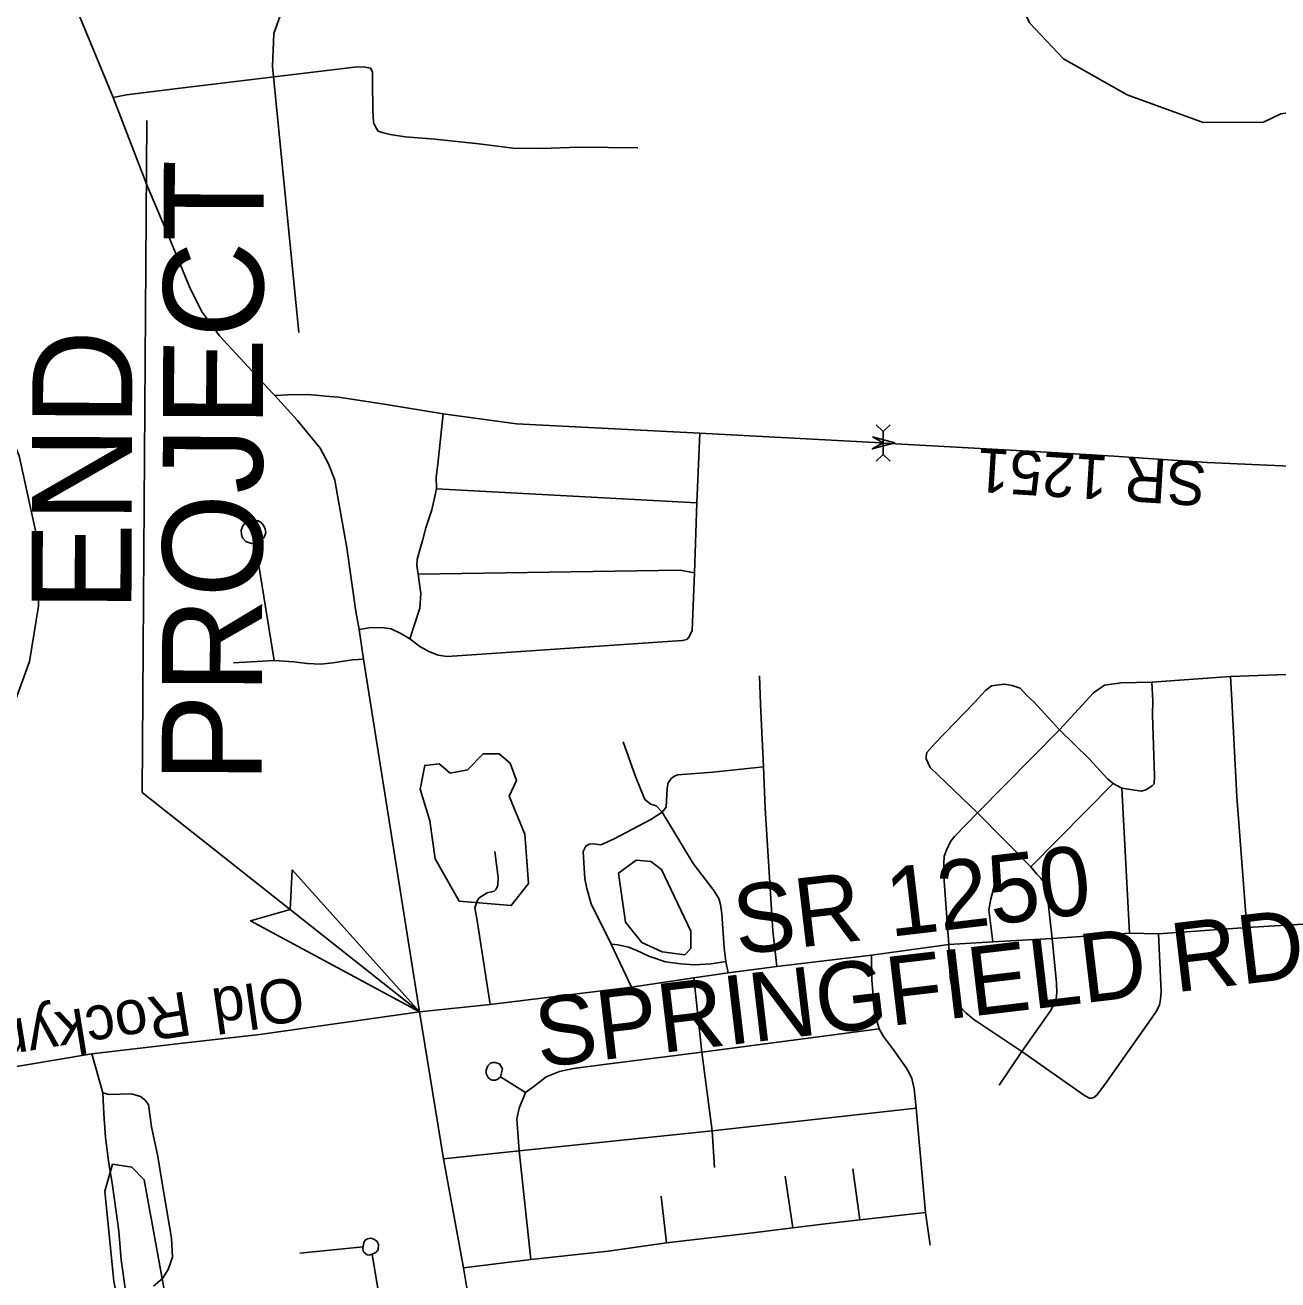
# Model space of a CAD drawing. Extents: x 2364794 to 2387902, y 795230 to 810426.
# Drawn here: x 2365657 to 2366377, y 801040 to 801761 of the extents above; entities that cross this region are included whole.
import ezdxf

# ---------------------------------------------------------------- set-up
doc = ezdxf.new("R2010")
doc.units = 0
for name, color, linetype in [('Default', 7, 'Continuous'), ('Old_Level_10', 7, 'Continuous'), ('Plot Label CELL', 7, 'Continuous'), ('User Information Notes CELL', 7, 'Continuous')]:
    doc.layers.add(name, color=color, linetype=linetype)

msp = doc.modelspace()

# ---------------------------------------------------------------- linework, layer by layer
at = {"layer": 'Default'}
for p, q in [((2365724.03, 801320.15), (2365726.66, 801706.52)), ((2366145.85, 801531.64), (2366149.86, 801527.81)), ((2366149.82, 801514.59), (2366149.86, 801527.81)), ((2366153.91, 801531.61), (2366149.86, 801527.81)), ((2366145.77, 801510.78), (2366149.82, 801514.59)), ((2366153.83, 801510.75), (2366149.82, 801514.59)), ((2365724.03, 801320.15), (2365883.31, 801194.17))]:
    msp.add_line(p, q, dxfattribs=at)
msp.add_lwpolyline([(2366143.64, 801524.67), (2366156.51, 801521.18), (2366143.62, 801517.77), (2366149.84, 801521.2)], close=True, dxfattribs=at)
msp.add_lwpolyline([(2365856.06, 801054.68), (2365854.33, 801054.22), (2365853.23, 801054.44), (2365852.59, 801054.87), (2365851.24, 801056.16), (2365850.8, 801057.91), (2365851, 801059.01)], dxfattribs=at)
at = {"layer": 'Old_Level_10'}
msp.add_lwpolyline([(2365810.14, 801275.75), (2365883.31, 801194.17), (2365786.22, 801246.47), (2365808.96, 801252.97)], close=True, dxfattribs=at)
at = {"layer": 'Plot Label CELL'}
for p, q in [((2366042.7, 801486.71), (2366044.51, 801526.78)), ((2366042.7, 801486.71), (2365893.12, 801494.87)), ((2366041.33, 801446.54), (2366042.7, 801486.71)), ((2365799.76, 801396.09), (2365788.94, 801463.66)), ((2365799.76, 801396.09), (2365776.41, 801394.77)), ((2366304.23, 801383.57), (2366349.47, 801386.86)), ((2366392.08, 801388.36), (2366349.47, 801386.86)), ((2366251.17, 801356.23), (2366204.14, 801308.59)), ((2366234.8, 801277.39), (2366282.05, 801325.43)), ((2366287.09, 801322.65), (2366282.05, 801325.43)), ((2366291.51, 801239.37), (2366287.09, 801322.65)), ((2366204.14, 801308.59), (2366234.8, 801277.39)), ((2366005.19, 801208.19), (2365993.61, 801232.94)), ((2366060.86, 801216.45), (2366059.49, 801222.98)), ((2366045.69, 801170.88), (2366040.96, 801213.55)), ((2366045.69, 801170.88), (2366147.48, 801184.4)), ((2365701.33, 801147.43), (2365695.01, 801169.89)), ((2366045.69, 801170.88), (2366051.52, 801125.68)), ((2366216.63, 801151.97), (2366229.58, 801171.31)), ((2365944.26, 801147.67), (2365929.96, 801156.75)), ((2366168.85, 801138.66), (2366051.52, 801125.68)), ((2366174.17, 801078.65), (2366168.85, 801138.66)), ((2366051.52, 801125.68), (2365940.61, 801114.12)), ((2366051.52, 801125.68), (2366052.84, 801104.67)), ((2365940.61, 801114.12), (2365897.22, 801109.53)), ((2365940.61, 801114.12), (2365947.34, 801051.63)), ((2366136.37, 801074.52), (2366132.41, 801103.77)), ((2366097.95, 801069.98), (2366093.59, 801099.64)), ((2366025.39, 801061.3), (2366022.24, 801088.12)), ((2366174.17, 801078.65), (2366136.37, 801074.52)), ((2366176.95, 801059.95), (2366174.17, 801078.65)), ((2365851, 801059.01), (2365814.54, 801055.42)), ((2365866.87, 800990.38), (2365856.06, 801054.68)), ((2365947.34, 801051.63), (2365908.58, 801046.96))]:
    msp.add_line(p, q, dxfattribs=at)
for points in [[(2365601.97, 802065.34), (2365608.14, 802036.91), (2365618.31, 801994.7), (2365629.39, 801945.94), (2365637.09, 801915.61), (2365644.63, 801882.94), (2365648.33, 801867), (2365652.04, 801856.05), (2365681.62, 801782.08), (2365707.36, 801719.77), (2365726.7, 801669.63), (2365740.76, 801635.99), (2365751.2, 801610.96), (2365758, 801596.99), (2365768.48, 801582.74), (2365799.1, 801549.63), (2365800.21, 801548.43)], [(2366008.94, 801690.82), (2365974.98, 801691.2), (2365953.65, 801690.49), (2365937.2, 801690.68), (2365917.47, 801693.12), (2365892.21, 801695.84), (2365875.1, 801697.21), (2365866.42, 801698.56), (2365861.95, 801699.63), (2365859.58, 801700.42), (2365858.27, 801702.53), (2365856.97, 801705.43), (2365856.46, 801712.54), (2365856.26, 801728.59), (2365856.28, 801734.64), (2365855.23, 801736.75), (2365852.08, 801737.28), (2365847.47, 801737.43), (2365744.23, 801724.9), (2365715, 801721.32), (2365707.36, 801719.77)], [(2366620.55, 801496.5), (2366482.99, 801503.36), (2366336.12, 801509.96), (2366282.43, 801513.49), (2366243.83, 801515.9), (2366150.3, 801521.11), (2366145.19, 801521.38), (2366044.51, 801526.78), (2365939.06, 801532.24), (2365896.96, 801538), (2365863.11, 801543.56), (2365836.88, 801547.42), (2365829.34, 801548.15), (2365823.73, 801548.7), (2365818.81, 801549.06), (2365807.58, 801548.93), (2365800.21, 801548.43)], [(2365800.21, 801548.43), (2365812.97, 801534.18), (2365826.25, 801518.17), (2365831.13, 801509.2), (2365834.61, 801499.72), (2365836.25, 801491.03), (2365841.49, 801460.93), (2365846.72, 801424.34), (2365848.61, 801413.99), (2365851.18, 801396.79), (2365883.31, 801194.17)], [(2365893.12, 801494.87), (2365892.97, 801501.53), (2365893.87, 801508.89), (2365896.96, 801538)], [(2365882.59, 801445.79), (2365881.91, 801450.7), (2365882.1, 801454.21), (2365883.52, 801459.64), (2365885.29, 801465.6), (2365887.07, 801472.43), (2365890.44, 801482.77), (2365893.12, 801494.87)], [(2365788.94, 801463.66), (2365791.13, 801464.13), (2365793.95, 801466.56), (2365795.03, 801469.42), (2365794.57, 801471.81), (2365793.89, 801473.56), (2365792.12, 801475.72), (2365790.57, 801476.36), (2365785.76, 801476.31), (2365783.59, 801475.64), (2365781.86, 801473.44), (2365780.79, 801471.02), (2365781.03, 801468.62), (2365781.7, 801466.65), (2365783.49, 801464.49), (2365786.76, 801463.43), (2365788.94, 801463.66)], [(2365877.72, 801408.62), (2365883.59, 801404.13), (2365888.67, 801401.3), (2365894.1, 801399.18), (2365899.27, 801398.37), (2365927.53, 801400.38), (2366028.73, 801407.3), (2366034.52, 801407.63), (2366036.98, 801408.15), (2366038.39, 801409.72), (2366039.98, 801413.4), (2366041.33, 801446.54)], [(2365877.72, 801408.62), (2365883.58, 801426.14), (2365884.13, 801434.56), (2365882.59, 801445.79)], [(2366041.33, 801446.54), (2366033.26, 801447.98), (2365882.59, 801445.79)], [(2365848.61, 801413.99), (2365855.63, 801415.01), (2365863, 801414.81), (2365867.04, 801414.27), (2365872.64, 801411.62), (2365877.72, 801408.62)], [(2365851.18, 801396.79), (2365844.86, 801396.46), (2365833.45, 801394.75), (2365826.6, 801394.07), (2365818.71, 801394.27), (2365811.16, 801395.35), (2365799.76, 801396.09)], [(2366081.05, 801334.88), (2366079.44, 801370.96), (2366078.78, 801387.27)], [(2366251.17, 801356.23), (2366270.83, 801377.56), (2366277.13, 801382), (2366286.74, 801383.19), (2366304.23, 801383.57)], [(2366304.23, 801383.57), (2366304.78, 801372.85), (2366304.66, 801364.76), (2366305.85, 801329.58), (2366305.66, 801325.2), (2366304.56, 801324.11), (2366300.87, 801321.67), (2366298.28, 801320.99), (2366287.09, 801322.65)], [(2366349.47, 801386.86), (2366350.29, 801373.24), (2366353.17, 801317.73), (2366358.84, 801242.59)], [(2366204.14, 801308.59), (2366176.81, 801334.6), (2366174.59, 801339.61), (2366174.57, 801341.14), (2366174.98, 801343.12), (2366179.76, 801348.62), (2366202.3, 801371.99), (2366208.74, 801378.92), (2366212.2, 801381.57), (2366219.41, 801382.52), (2366224.01, 801381.68), (2366228.62, 801380.21), (2366232.46, 801376.03), (2366236.4, 801372.28), (2366251.17, 801356.23)], [(2366282.05, 801325.43), (2366278.74, 801328.05), (2366268.38, 801339.32), (2366251.17, 801356.23)], [(2366022.91, 801308.82), (2366019.38, 801312.49), (2366016.3, 801313.57), (2366012.79, 801316.17), (2366007.42, 801329.46), (2366000.48, 801349.28)], [(2366022.91, 801308.82), (2366025.07, 801311.68), (2366025.64, 801322.62), (2366026.26, 801325.68), (2366028.22, 801328.53), (2366030.38, 801329.85), (2366031.91, 801330.31), (2366052, 801331.8), (2366081.05, 801334.88)], [(2366088.81, 801220.19), (2366086.44, 801240.7), (2366082.13, 801311.07), (2366081.05, 801334.88)], [(2365993.61, 801232.94), (2365982.03, 801256.21), (2365979.55, 801264.94), (2365978.42, 801270.63), (2365977.42, 801286.34), (2365978.92, 801289.41), (2365980.87, 801290.54), (2365983.48, 801290.77), (2365987.64, 801290.16), (2365988.96, 801290.6), (2365995.27, 801293.51), (2366016.38, 801304.62), (2366022.91, 801308.82)], [(2366059.49, 801222.98), (2366058.55, 801230.85), (2366057.07, 801250.52), (2366056.37, 801255.75), (2366055.47, 801259.23), (2366052.59, 801263.81), (2366040.65, 801279.45), (2366022.91, 801308.82)], [(2366187.52, 801232.81), (2366184.55, 801274.33), (2366184.91, 801283.51), (2366186.17, 801287.04), (2366188.55, 801292.07), (2366190.93, 801294.94), (2366204.14, 801308.59)], [(2365923.88, 801198.32), (2365916.31, 801247.8), (2365915.16, 801253.9), (2365916.44, 801257.84), (2365917.73, 801259.61), (2365922.3, 801262.5), (2365926.23, 801263.39), (2365927.3, 801264.5), (2365927.95, 801265.82), (2365928.38, 801267.12), (2365928.56, 801271.28), (2365926.69, 801286.36)], [(2366212.86, 801234.35), (2366210.51, 801252.7), (2366211.79, 801259.04), (2366216.22, 801275.46)], [(2366234.8, 801277.39), (2366238.12, 801273.26), (2366240.32, 801271.09), (2366242.54, 801268.04), (2366243.2, 801266.52), (2366243.89, 801263.46), (2366246.94, 801236.16)], [(2365883.31, 801194.17), (2365923.88, 801198.32), (2366005.19, 801208.19), (2366040.96, 801213.55), (2366060.86, 801216.45), (2366088.81, 801220.19), (2366143.18, 801226.76), (2366187.52, 801232.81), (2366212.86, 801234.35), (2366246.94, 801236.16), (2366291.51, 801239.37), (2366308.13, 801238.86), (2366358.84, 801242.59), (2366400.79, 801245.11), (2366444.48, 801245.73), (2366502.8, 801248.97), (2366582.15, 801253.06), (2366608.57, 801253.98)], [(2366059.49, 801222.98), (2366050.97, 801221.6), (2366041.36, 801221.09), (2366033.49, 801221.68), (2366024.74, 801222.92), (2366015.08, 801226.12), (2366007.85, 801229.55), (2366003.45, 801231.26), (2365997.31, 801232.53), (2365993.61, 801232.94)], [(2366229.58, 801171.31), (2366201.88, 801189.66), (2366197.47, 801193.56), (2366193.72, 801197.44), (2366191.28, 801201.79), (2366189.71, 801206.38), (2366188.34, 801213.81), (2366187.52, 801232.81)], [(2366229.58, 801171.31), (2366265.64, 801146.02), (2366268.49, 801144.54), (2366269.58, 801144.53), (2366270.9, 801144.76), (2366272.64, 801146.1), (2366278.26, 801153.57), (2366303.96, 801190.08), (2366306.78, 801194.27), (2366308.7, 801197.99), (2366309.35, 801201.28), (2366309.72, 801205.64), (2366308.13, 801238.86)], [(2366229.58, 801171.31), (2366246, 801194.62), (2366247.93, 801198.36), (2366249.21, 801201.64), (2366249.63, 801205.15), (2366249.58, 801210.82), (2366246.94, 801236.16)], [(2366147.48, 801184.4), (2366146.13, 801188.96), (2366144.76, 801196.39), (2366143.31, 801212.55), (2366143.18, 801226.76)], [(2365315.53, 801105.92), (2365323.19, 801107.64), (2365358.96, 801112.59), (2365378.31, 801116.43), (2365438.99, 801127.01), (2365522.01, 801140.45), (2365598.04, 801153.58), (2365695.01, 801169.89), (2365750.59, 801176.37), (2365791.61, 801181.15), (2365883.31, 801194.17)], [(2365883.31, 801194.17), (2365897.22, 801109.53), (2365908.58, 801046.96), (2365916.44, 800999.66), (2365925.73, 800934.59), (2365949.43, 800797.29), (2365960.28, 800728.51), (2365965.75, 800710.79), (2365969.29, 800705.11), (2365974.01, 800699.16), (2365986.96, 800688.84), (2366029.57, 800657.45), (2366052.09, 800641.03), (2366065.31, 800632.03)], [(2366168.85, 801138.66), (2366167.66, 801149.79), (2366166.31, 801155.69), (2366165.18, 801158.3), (2366163.19, 801161.79), (2366155.89, 801172.22), (2366150.14, 801179.81), (2366147.48, 801184.4)], [(2365944.26, 801147.67), (2365949.04, 801151.22), (2365956.24, 801156.78), (2365963.87, 801159.7), (2365971.8, 801161.5), (2365990.91, 801164.07), (2366045.69, 801170.88)], [(2365929.96, 801156.75), (2365928.46, 801155.43), (2365926.94, 801154.76), (2365925.4, 801154.74), (2365924.09, 801155.15), (2365922.76, 801156.25), (2365921.65, 801158.65), (2365921.64, 801160.61), (2365922.71, 801163.02), (2365924.23, 801164.56), (2365925.52, 801165.01), (2365926.83, 801165.03), (2365929.25, 801164.16), (2365929.92, 801163.31), (2365931.02, 801161.33), (2365929.96, 801156.75)], [(2365701.33, 801147.43), (2365701.9, 801135.45), (2365702.87, 801121.84), (2365704.84, 801106.8), (2365706.63, 801095.63), (2365708.22, 801084.66), (2365710.6, 801068), (2365711.96, 801051.54), (2365714.34, 801033.87)], [(2365730.4, 801036.45), (2365735.7, 801040.7), (2365738.97, 801045.97), (2365741.43, 801053.07), (2365740.86, 801064.03), (2365735.68, 801094.51), (2365732.9, 801110.97), (2365729.3, 801128.04), (2365727.52, 801140.84), (2365725.49, 801143.49), (2365723.06, 801145.32), (2365717.79, 801146.96), (2365711.28, 801146.78), (2365704.99, 801146.6), (2365701.33, 801147.43)], [(2365940.61, 801114.12), (2365939.36, 801132.56), (2365940.61, 801138.69), (2365944.26, 801147.67)], [(2365747.24, 800958.36), (2365730.08, 800956.45), (2365722.86, 800967.31), (2365707.62, 801039.09), (2365702.46, 801090.93), (2365706.9, 801106.45), (2365718.09, 801104.78), (2365725.18, 801097.53), (2365748.23, 800970.27), (2365747.24, 800958.36)], [(2366136.37, 801074.52), (2366116.45, 801072.15), (2366097.95, 801069.98)], [(2366097.95, 801069.98), (2366074.99, 801067.02), (2366025.39, 801061.3)], [(2365851, 801059.01), (2365851.42, 801061.42), (2365852.07, 801062.73), (2365853.37, 801063.61), (2365855.33, 801063.86), (2365857.1, 801063.42), (2365858.85, 801062.14), (2365859.75, 801060.39), (2365859.56, 801057.32), (2365858.25, 801055.78), (2365856.06, 801054.68)], [(2366025.39, 801061.3), (2365991.85, 801056.55), (2365947.34, 801051.63)]]:
    msp.add_lwpolyline(points, dxfattribs=at)
at = {"layer": 'User Information Notes CELL'}
for points in [[(2365379.05, 802102.57), (2365470.95, 801900.08), (2365477.96, 801750.79), (2365481.93, 801730.78), (2365499.6, 801689.93), (2365530.09, 801651.97), (2365602.48, 801597.05), (2365616.25, 801583.55), (2365637.64, 801549.14), (2365653.32, 801513.75), (2365665.04, 801459.27), (2365664.43, 801427.34), (2365659.16, 801395.43), (2365648.88, 801367)], [(2366462.41, 801518), (2366392, 801712.25), (2366378.43, 801710.32), (2366368.56, 801705.65), (2366333.77, 801705.35), (2366290.1, 801721.35), (2366253.45, 801741.93), (2366234.01, 801762.67), (2366219.12, 801796.18), (2366210.57, 801823.43), (2366195.87, 801842.41), (2366156.6, 801865.73), (2366121.86, 801873.61), (2366084.25, 801871.46), (2366068.93, 801868.55), (2366036.28, 801868.24), (2366022.41, 801874.52), (2366016.73, 801882.62), (2366015.99, 801892.69)], [(2365813.95, 801584.6), (2365798.93, 801737.53), (2365799.65, 801756.65), (2365813.61, 801795.86)], [(2365945.99, 801267.88), (2365943.86, 801296.21), (2365934.8, 801318.01), (2365939.12, 801327.08), (2365935.52, 801337.14), (2365929.21, 801342.52), (2365919.89, 801342.44), (2365910.9, 801333.3), (2365900.92, 801331.36), (2365894.62, 801336.74), (2365886.4, 801335.79), (2365883.69, 801322.03), (2365889.38, 801303.96), (2365892.36, 801282.06), (2365906.18, 801257.64), (2365936.06, 801255.14), (2365945.99, 801267.88)], [(2366039.26, 801230.49), (2366035.81, 801226.78), (2366022.82, 801228.57), (2366011.14, 801233.86), (2366001.73, 801245.6), (2365997.8, 801273.82), (2366007.94, 801281.23), (2366016.23, 801280.44), (2366022.49, 801275.93), (2366039.24, 801240.56), (2366039.26, 801230.49)]]:
    msp.add_lwpolyline(points, dxfattribs=at)

# ---------------------------------------------------------------- texts
at = {"layer": 'Default'}
for s, height, rotation, p in [('PROJECT', 57.409, 89.79762, (2365792.56, 801325.52)), ('END', 57.409, 89.79762, (2365717.77, 801424.05)), ('SR 1250', 39.628, 6.73691, (2366066.17, 801226.79)), ('SPRINGFIELD RD', 39.628, 6.73691, (2365952.18, 801162.08)), ('Old', 25.362, 188.07897, (2365814.99, 801214.53)), ('Rockymount', 25.362, 189.18517, (2365749.49, 801206.03))]:
    msp.add_text(s, height=height, rotation=rotation, dxfattribs=at).set_placement(p)
at = {"layer": 'Plot Label CELL'}
msp.add_text('SR 1251', height=25.362, rotation=176.4176, dxfattribs=at).set_placement((2366336.21, 801510.12))

doc.saveas('drawing.dxf')
